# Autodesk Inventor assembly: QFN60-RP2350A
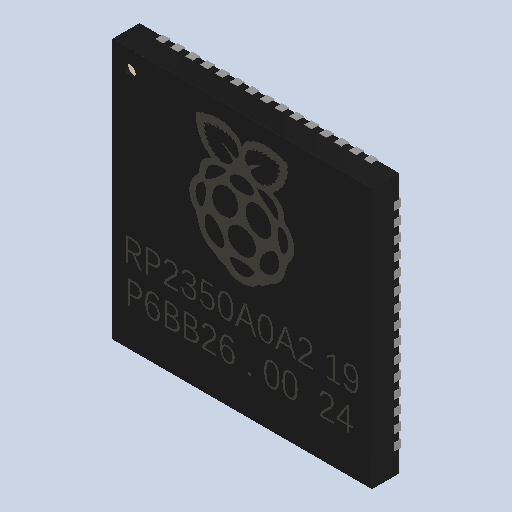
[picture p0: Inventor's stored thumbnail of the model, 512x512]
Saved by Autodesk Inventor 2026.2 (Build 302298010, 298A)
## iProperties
Created: 2026-10
Part Number: QFN60-RP2350A
Document SubType Name: Assembly
Designer: mel
Author: mel
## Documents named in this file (7)
- D:\travail\année 2026-2027\1 sti2d IT\poubelle à verre\raspberry-pico-2-microcontroller-rp2350-1.snapshot.5\raspberry_pico_2\raspberry_pico_2\QFN60-RP2350A.iam
- D:\travail\année 2026-2027\1 sti2d IT\poubelle à verre\raspberry-pico-2-microcontroller-rp2350-1.snapshot.5\raspberry_pico_2\raspberry_pico_2\Scale.ipt
- D:\travail\année 2026-2027\1 sti2d IT\poubelle à verre\raspberry-pico-2-microcontroller-rp2350-1.snapshot.5\raspberry_pico_2\raspberry_pico_2\ShapeString012.iam
- D:\travail\année 2026-2027\1 sti2d IT\poubelle à verre\raspberry-pico-2-microcontroller-rp2350-1.snapshot.5\raspberry_pico_2\raspberry_pico_2\ShapeString024.iam
- D:\travail\année 2026-2027\1 sti2d IT\poubelle à verre\raspberry-pico-2-microcontroller-rp2350-1.snapshot.5\raspberry_pico_2\raspberry_pico_2\Array008.iam
- D:\travail\année 2026-2027\1 sti2d IT\poubelle à verre\raspberry-pico-2-microcontroller-rp2350-1.snapshot.5\raspberry_pico_2\raspberry_pico_2\Chamfer.ipt
- D:\travail\année 2026-2027\1 sti2d IT\poubelle à verre\raspberry-pico-2-microcontroller-rp2350-1.snapshot.5\raspberry_pico_2\raspberry_pico_2\Pocket001.ipt
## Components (6 placed, 6 different names)
1. 2664
2. 2676 [sub-assembly]
3. 2689 [sub-assembly]
4. 2754 [sub-assembly]
5. 2755
6. 2756
